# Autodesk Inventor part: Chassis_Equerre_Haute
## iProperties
Created: 2008-12
Part Number: Chassis_Equerre_Haute
Document SubType Name: Modeling
Designer: claivier
Author: claivier
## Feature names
1. Extrusion1
2. Extrusion2
3. Perçage1 [Hole]
4. Perçage2 [Hole]
5. Perçage3 [Hole]
6. Perçage4 [Hole]
7. Extrusion3
